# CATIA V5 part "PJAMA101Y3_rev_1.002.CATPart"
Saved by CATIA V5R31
Part number: JAMA101Y3
Revision: 1
Nomenclature: BRACE_R
Source: Unknown
Property "部品番号(A社)": "JAMA101Y3"
Property "部品名称(A社)": "BRACE_R"
Property "Version(A社)": "1"
Property "材質(A社)": "SPCN2"
Property "板厚": "0.9"
Bounding box of the stored display mesh (mm): x 4183.201 to 4343.309, y 289.334 to 563.489, z 678 to 858
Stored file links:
  \\solize.local\damia\dept\DDE_Design\10_order\2305701_JAMA_変換検証STEP3_お手本モデル作成\work\02_マツダ_板金\10_CATIA_V5\231211\PJAMA101Y3_rev_1.002.CATPart
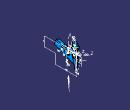
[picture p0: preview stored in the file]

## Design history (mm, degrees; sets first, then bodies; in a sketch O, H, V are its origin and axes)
TTRSSet1
f4a2d38f3ddc11d3a929006094b99c4b_11 "CATTPSSet"
Set1
  DatumSurface1 "OPEN_SHELL #620"
Set2 "DATUM"
  Point1: stored without definition
  Point2: stored without definition
  AxisSystem1: origin (4240, 421, 701.5), X (-0.3992, -0.3413, 0.851), Y (0.1668, 0.8856, 0.4334), Z (-0.9016, 0.315, -0.2966)
  AxisSystem2: origin (4277.5, 523, 760), X (0.1668, 0.8856, 0.4334), Y (0.3992, 0.3413, -0.851), Z (-0.9016, 0.315, -0.2966)
  Point3 to Point6: stored without definition
  Plane1: stored without definition
  Plane2: stored without definition
  AxisSystem3: origin (4294.2416, 520.4956, 830), X (1, 0, 0), Y (0, 1, 0), Z (0, 0, 1)
  AxisSystem4: origin (4310.9156, 563.489, 830), X (1, 0, 0), Y (0, 1, 0), Z (0, 0, 1)
Set3 "CURVE"
  DatumSurface2
  DatumCurve1
  DatumSurface3 to DatumSurface5
  DatumCurve2
  DatumCurve3
  Circle1: stored without definition
  Sketch1 on XY plane of AxisSystem3, origin (4294.2416, 520.4956, 830), H (-1, 0, 0), V (0, -1, 0)
    point P1 (-16.6741, -27.9933)
    line L1 (-16.6741, -27.9933) -> (-16.6741, -42.9933)
    point P2 (-16.6741, -42.9933)
    line L2 (-16.6741, -42.9933) -> (-18.0138, -37.9933)
    construction line L3 (-18.0138, -37.9933) -> (-15.3343, -37.9933)
    line L4 (-15.3343, -37.9933) -> (-16.6741, -42.9933)
    angle L4 L2 = 30
    distance L3 P2 = 5
    distance P1 L3 = 10
    vertical: L1 V
    horizontal: L3 H
    symmetry: L2 L4 L1
Body1 (main body)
